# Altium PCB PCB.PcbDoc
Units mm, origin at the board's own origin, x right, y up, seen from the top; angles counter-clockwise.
Board outline 41 x 25.36 mm, 2 copper layers (TOP, BOTTOM), stack 1.586 mm thick; 29 components, 7 nets, 66 pads, 24 vias.
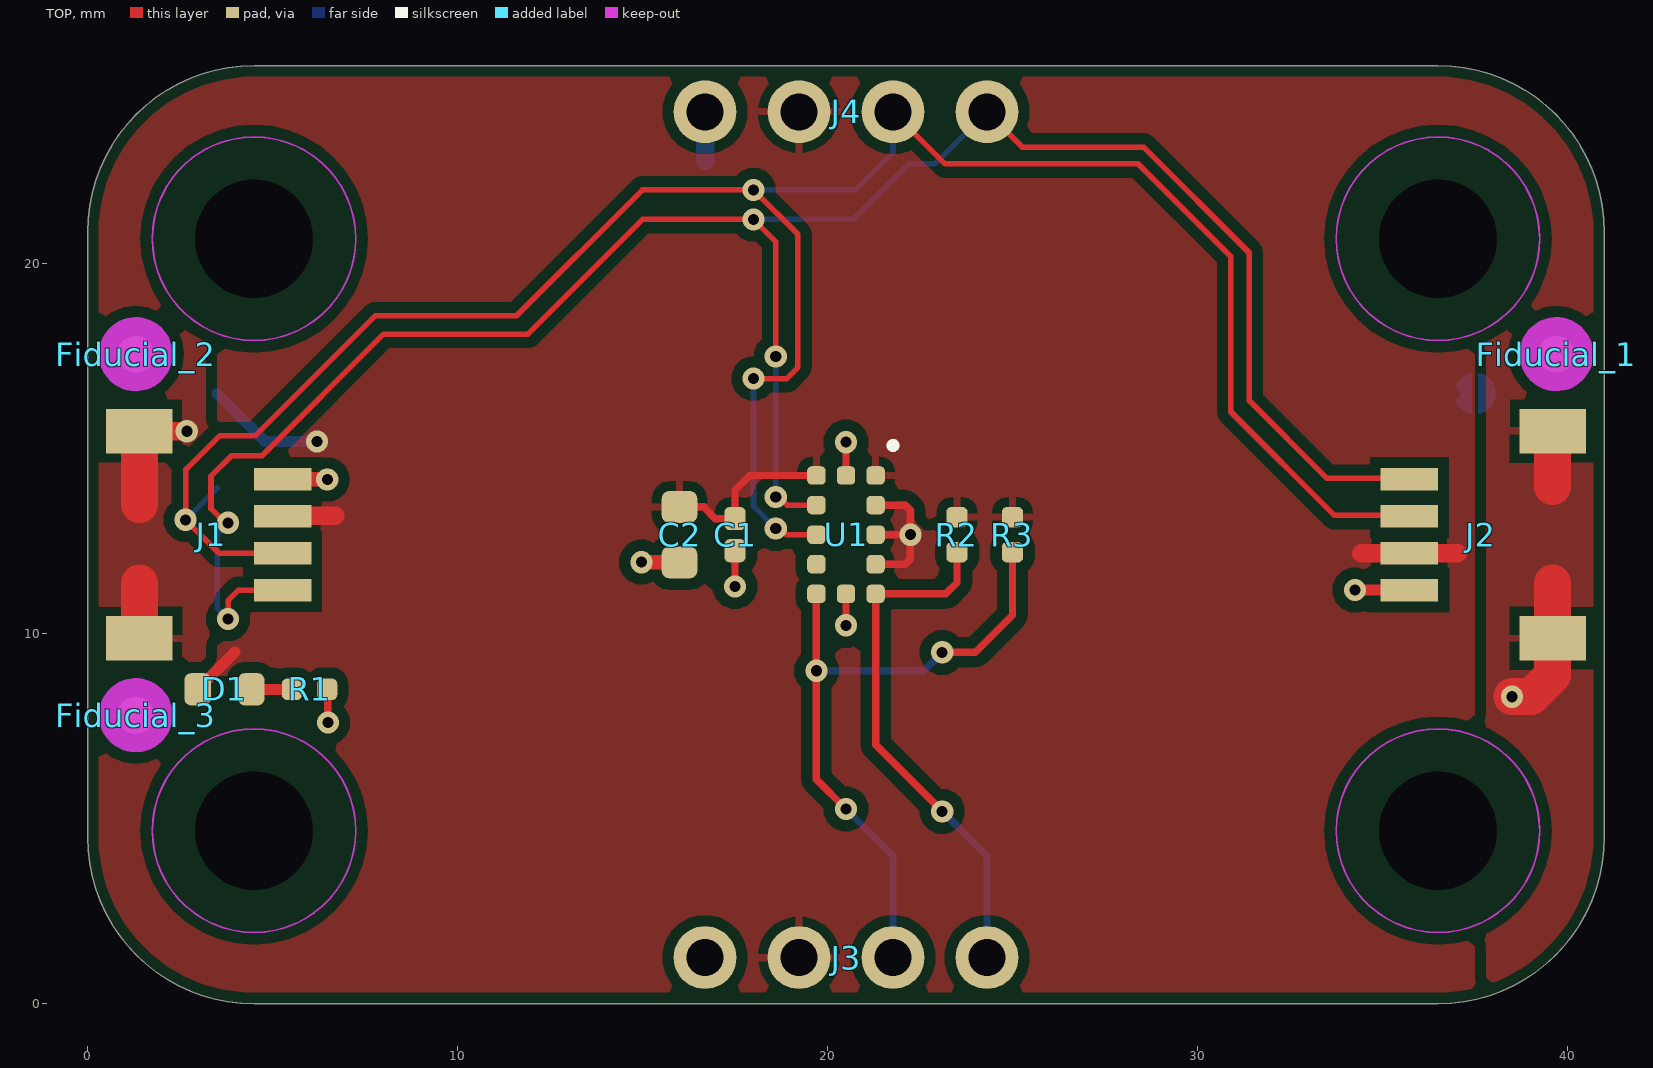
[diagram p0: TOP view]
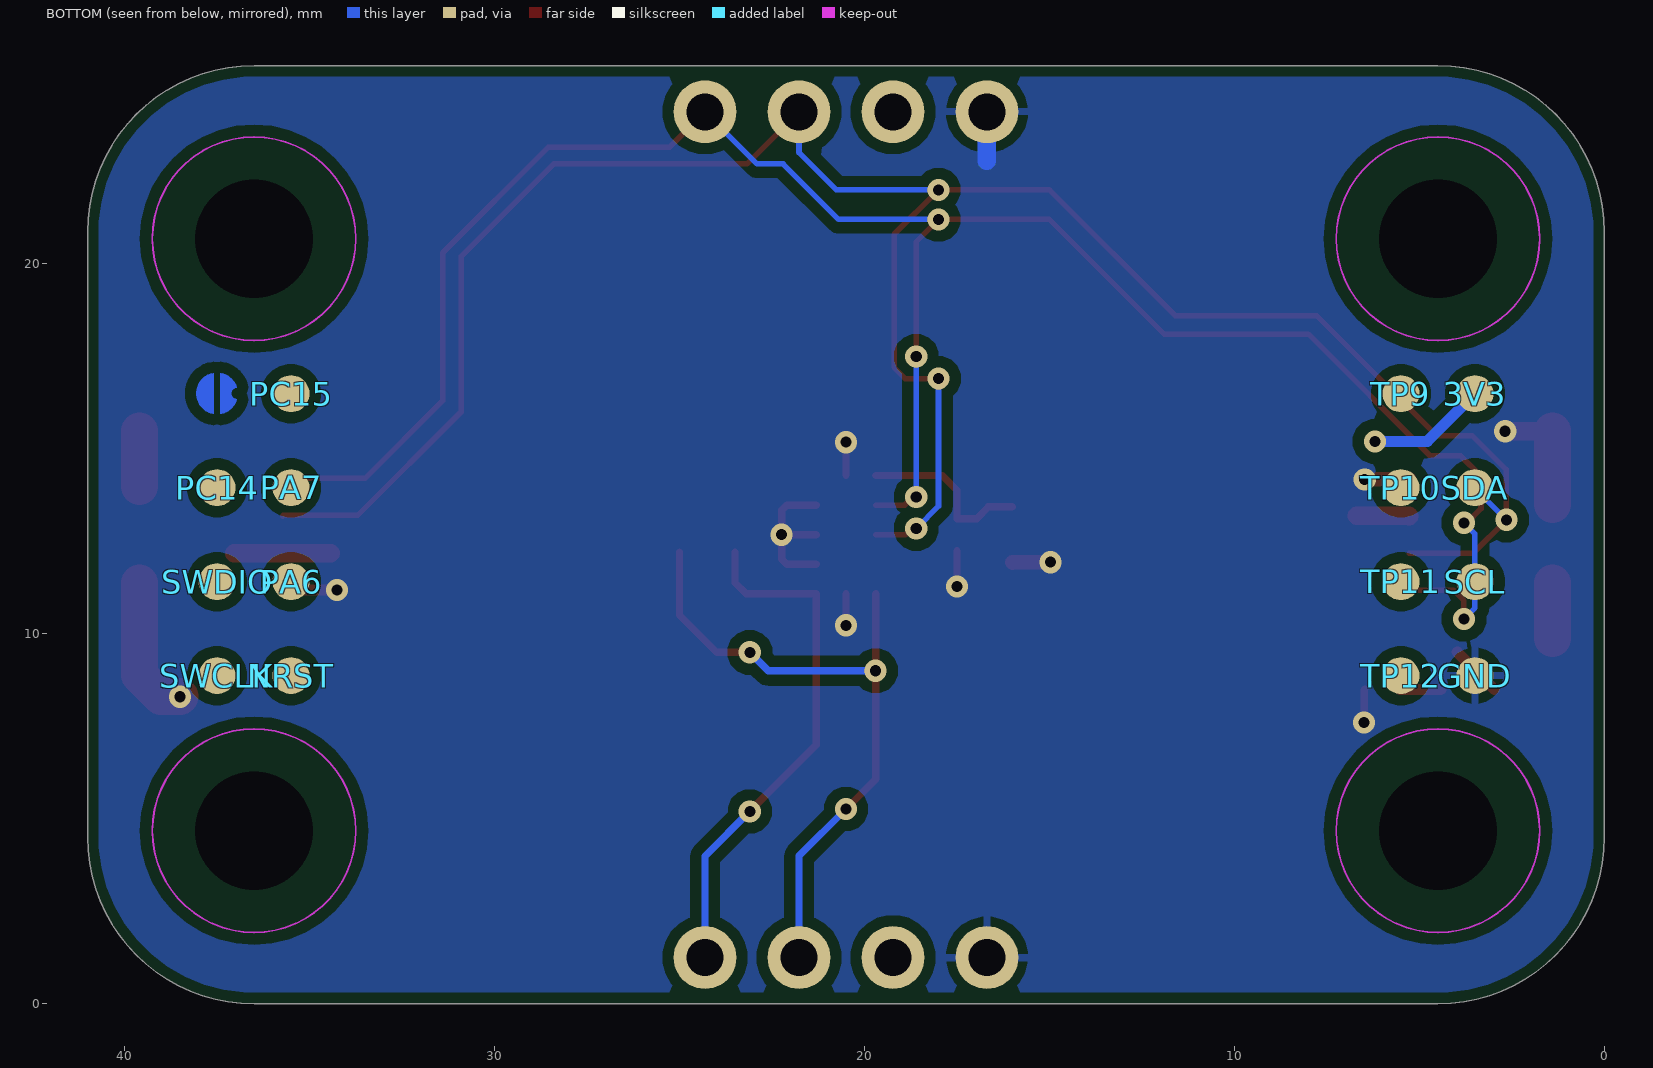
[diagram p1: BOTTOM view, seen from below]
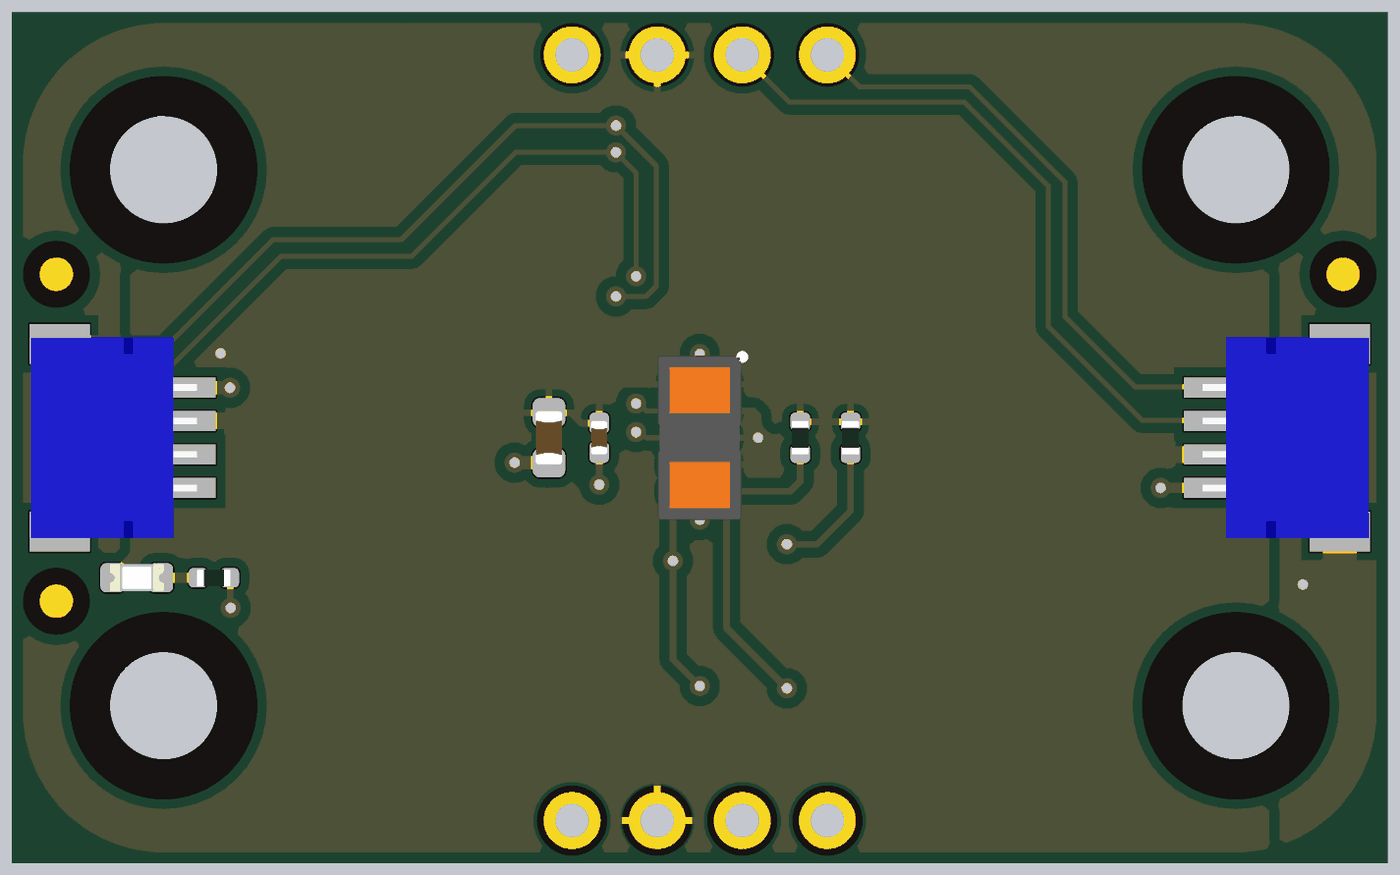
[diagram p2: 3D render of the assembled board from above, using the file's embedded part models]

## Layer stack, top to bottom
Top Solder: solder mask 0.01, Solder Resist, Dk 3.5
TOP: signal copper 0.018
Dielectric: core 1.55, FR-4, Dk 4.8
BOTTOM: signal copper 0.018
Bottom Solder: solder mask 0.01, Solder Resist, Dk 3.5

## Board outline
0,4.5 ccw(c4.5,4.5) 4.5,0 36.5,0 ccw(c36.5,4.5) 41,4.5 41,20.86 ccw(c36.5,20.86) 36.5,25.36 4.5,25.36 ccw(c4.5,20.86) 0,20.86

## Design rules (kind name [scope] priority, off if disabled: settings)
BoardOutlineClearance Mousebites [(ObjectKind = 'Pad') And (Name = 'Free-MOUSEBITE')] p1: gap=0 ignorepadtopadclearanceinfootprint=FALSE
BoardOutlineClearance Silks [(OnLayer('Top Overlay') OR OnLayer('Bottom Overlay'))] p2: gap=0 ignorepadtopadclearanceinfootprint=FALSE
BoardOutlineClearance [All] p3: gap=0.3 ignorepadtopadclearanceinfootprint=FALSE
Clearance COPPER_0.3mm [All] p1: gap=0.127 ignorepadtopadclearanceinfootprint=FALSE except(0.3: Arc-Fill Arc-Poly Arc-Region Track-Fill Track-Poly Track-Region SMDPad-Fill SMDPad-Poly SMDPad-Region THPad-Fill THPad-Poly THPad-Region Via-Fill Via-Poly Via-Region Fill-Fill Fill-Poly Fill-Region Poly-Poly Poly-Region Region-Region)
Clearance "Generic clearance 0.15mm" [All] p2: gap=0.15 ignorepadtopadclearanceinfootprint=FALSE
ComponentClearance [All] p1: gap=0.2 collisioncheckmode=3 verticalgap=0 showdistances=TRUE
DiffPairsRouting USB [InDifferentialPairClass('USB')] p1: maxlimit=0.15 minlimit=0.15 mostfreqgap=0.15 toplayer_minwidth=0.15 toplayer_maxwidth=0.21 toplayer_prefwidth=0.2 bottomlayer_minwidth=0.15 bottomlayer_maxwidth=0.21 bottomlayer_prefwidth=0.2 impedanceprofiledriven=TRUE impedanceprofileid={E6B00C31-4C8E-439C-824F-D2B2CDC26F9C} impedanceprofilevalue=90.000000 maxuncoupledlength=12.7
Height [All] p1: minheight=0 maxheight=30 prefheight=12.7
HoleSize [All] p1: absolutevalues=TRUE maxlimit=30 minlimit=0.3 maxpercent=80.000 minpercent=20.000
HoleToHoleClearance [All] p1: gap=0.25 allowstackedmicrovias=FALSE
MinimumAnnularRing [All] p1: minimumring=0.15
PlaneConnect [All] p1: pad.planeconnectstyle=Relief pad.reliefexpansion=0.508 pad.reliefentries=4 pad.reliefconductorwidth=0.254 pad.reliefairgap=0.254 via.planeconnectstyle=Direct via.reliefexpansion=0.508 via.reliefentries=4 via.reliefconductorwidth=0.254 via.reliefairgap=0.254
PolygonConnect [All] p1: thpad.connectstyle=Relief thpad.reliefconductorwidth=0.2 thpad.reliefentries=4 thpad.polygonreliefangle="90 Angle" thpad.airgapwidth=0.254 smdpad.connectstyle=Relief smdpad.reliefconductorwidth=0.2 smdpad.reliefentries=4 smdpad.polygonreliefangle="90 Angle" smdpad.airgapwidth=0.254 via.connectstyle=Direct via.reliefconductorwidth=0.254 via.reliefentries=4 via.polygonreliefangle="90 Angle" via.airgapwidth=0.254
RoomDefinition TOP [InComponentClass('TOP')] p1: confinementstyle=ConfineIn formatcopy=TRUE lockcomponents=FALSE outline 44.8,6 53.5,6 53.5,18.1 44.8,18.1
RoutingVias StandardVias [All] p1: holewidth=0.3 width=0.6 viastyle="Through Hole" minholewidth=0.3 minwidth=0.6 maxholewidth=0.3 maxwidth=0.6
SMDToCorner [All] p1: distance=39370
SilkToSilkClearance [All] p1: silktosilkclearance=0.2
SilkToSolderMaskClearance [IsPad] p1: minsilkscreentomaskgap=0.15 clearancetoexposedcopper=TRUE
SolderMaskExpansion VIAtented [IsVia] p1: expansion=0.102 istentingtop=TRUE
SolderMaskExpansion [All] p2: expansion=0.05 istentingtop=FALSE
UnConnectedPin [All] p1:
UnRoutedNet [NOT WithinRoom('K36')] p1: checkbadconnections=TRUE
ViasUnderSMD [All] p1: allowed=FALSE
Width StandardTraces [All] p1: maxlimit=5 minlimit=0.15 preferedwidth=0.15 minimp=50.000000 maximp=50.000000 favimp=50.000000
21 further rules are at their usual default settings.

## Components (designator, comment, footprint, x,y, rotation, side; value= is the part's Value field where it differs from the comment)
3V3 "Test point 1.00mm" TP-1.00MM 3.5,16.49 r90 bottom
C1 "0402B104K160CT" CAP-0402 17.5,12.68 r270 top value=100nF
C2 "GRM188R61C475KAAJD" CAP-0603 16,12.68 r90 top value=4.7µF
D1 "HSMG-C190" LEDC1608X80N-AK 3.7,8.5 r180 top
Fiducial_1 "Fiducial mark 1mm" "Fiducial mark 1mm-Footprint-1" 39.7,17.56 r270 top
Fiducial_2 "Fiducial mark 1mm" "Fiducial mark 1mm-Footprint-1" 1.3,17.56 r270 top
Fiducial_3 "Fiducial mark 1mm" "Fiducial mark 1mm-Footprint-1" 1.3,7.8 r270 top
GND "Test point 1.00mm" TP-1.00MM 3.5,8.87 r90 bottom
J1 "SM04B-SRSS-TB(LF)(SN)" SM04B-SRSS-TB(LF)(SN)-Footprint-1 3.337,12.68 r90 top locked
J2 "SM04B-SRSS-TB(LF)(SN)" SM04B-SRSS-TB(LF)(SN)-Footprint-1 37.663,12.68 r270 top locked
J3 "HEADER TH 2.54mm VERT. 1x004POS" "PIN HEADER 2.54mm VERT. 1x4POS-Footprint-1"#1 20.5,1.25 r0 top
J4 "HEADER TH 2.54mm VERT. 1x004POS" "PIN HEADER 2.54mm VERT. 1x4POS-Footprint-1"#2 20.5,24.11 r0 top
NRST "Test point 1.00mm" TP-1.00MM 35.5,8.87 r180 bottom
PA6 "Test point 1.00mm" TP-1.00MM 35.5,11.41 r180 bottom
PA7 "Test point 1.00mm" TP-1.00MM 35.5,13.95 r180 bottom
PC14 "Test point 1.00mm" TP-1.00MM 37.5,13.95 r180 bottom
PC15 "Test point 1.00mm" TP-1.00MM 35.5,16.49 r180 bottom
R1 "CRCW04021K00FKEDC" RES-0402 6,8.5 r180 top value=1k
R2 "CRCW040210K0FKED" RES-0402 23.5,12.68 r270 top value=10k
R3 "CRCW040210K0FKED" RES-0402 25,12.68 r90 top value=10k
SCL "Test point 1.00mm" TP-1.00MM 3.5,11.41 r90 bottom
SDA "Test point 1.00mm" TP-1.00MM 3.5,13.95 r90 bottom
SWCLK "Test point 1.00mm" TP-1.00MM 37.5,8.87 r180 bottom
SWDIO "Test point 1.00mm" TP-1.00MM 37.5,11.41 r180 bottom
TP9 "Test point 1.00mm" TP-1.00MM 5.5,16.49 r0 bottom
TP10 "Test point 1.00mm" TP-1.00MM 5.5,13.95 r0 bottom
TP11 "Test point 1.00mm" TP-1.00MM 5.5,11.41 r0 bottom
TP12 "Test point 1.00mm" TP-1.00MM 5.5,8.87 r0 bottom
U1 "VL53L4CDV0DH/1" VL53L4CDV0DH/1 20.5,12.68 r90 top

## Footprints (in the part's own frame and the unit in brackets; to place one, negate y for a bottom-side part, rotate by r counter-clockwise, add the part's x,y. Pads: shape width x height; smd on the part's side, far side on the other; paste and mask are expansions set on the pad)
CAP-0402 [mm] "Chip Capacitor, 2-Leads, Body  0402 (in) 1005 (mm), IPC Medium Density"
  rrect52% 0.63x0.58 smd mask+0.05: 1(-0.435,0) 2(0.435,0)
  body extent -0.5,-0.25 0.5,0.25, height 0.5
CAP-0603 [mm] "Chip Capacitor, Body 0603 imperial,1.6x0.8mm, IPC High Density"
  rrect51% 0.87x0.97 smd mask+0.05: 1(-0.75,0) 2(0.75,0)
  body extent -0.8,-0.4 0.8,0.4, height 0.8
"Fiducial mark 1mm-Footprint-1" [mm]
  round 1 smd paste-10 mask+0.5: 1(0,0)
  TOP keep-out circle w1: c0,0 r0.5
LEDC1608X80N-AK [mm]
  rrect50% 0.72x0.87 smd: A(0.725,0) C(-0.725,0)
  body extent -0.8,-0.4 0.8,0.4, height 0.79
"PIN HEADER 2.54mm VERT. 1x4POS-Footprint-1"#1 [mm]
  round 1.7 hole 1 mask+0.2: 1(-3.81,0) 2(-1.27,0) 3(1.27,0) 4(3.81,0)
"PIN HEADER 2.54mm VERT. 1x4POS-Footprint-1"#2 [mm]
  round 1.7 hole 1 mask+0.1: 1(-3.81,0) 2(-1.27,0) 3(1.27,0) 4(3.81,0)
RES-0402 [mm] "Chip Resistor, 2-Leads, Body  0402 (in) 1005 (mm), IPC Medium Density"
  rrect51% 0.55x0.58 smd mask+0.05: 1(-0.475,0) 2(0.475,0)
  body extent -0.5,-0.25 0.5,0.25, height 0.34
SM04B-SRSS-TB(LF)(SN)-Footprint-1 [mm]
  rect 0.6x1.55 smd mask+0.05: 1(1.5,-1.937) 2(0.5,-1.937) 3(-0.5,-1.937) 4(-1.5,-1.937)
  rect 1.2x1.8 smd mask+0.05: FIX(-2.8,1.938) FIX(2.8,1.938)
  body extent -3,-2.16 3,2.8, height 2.98
TP-1.00MM [mm]
  rrect100% 1x1 smd paste-2.54: X(0,0)
VL53L4CDV0DH/1 [mm]
  rrect50% 0.5x0.5 smd mask+0.07: 1(1.6,-0.8) 2(0.8,-0.8) 3(0,-0.8) 4(-0.8,-0.8) 5(-1.6,-0.8) 6(-1.6,0) 7(-1.6,0.8) 8(-0.8,0.8) 9(0,0.8) 10(0.8,0.8) 11(1.6,0.8) 12(1.6,0)
  silkscreen extent 2.36,-1.32 2.46,-1.22, body extent -2.45,-1.25 2.45,1.25, height 1.6

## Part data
3V3 GND NRST PA6 PA7 PC14 PC15 SCL SDA SWCLK SWDIO TP9 TP10 TP11 TP12: library part UT0013-A.6, Manufacturer="This is not a component"
C1: library part C0012-A.15, "CAP CHIP 0402 100nF 10% 16V X7R", Case Code (Imperial)=0402, Dielectric=X7R, Manufacturer=Walsin, Tolerance=10%, Voltage=16V
C2: library part C0054-A.16, "CAP CHIP 0603 4.7uF 10% 16V X5R", Case Code (Imperial)=0603, Dielectric=X5R, Manufacturer=Murata, Manufacturer 3="Samsung Electro-Mechanics", Part number 2=GRM188R61C475KE11D, Part number 3=CL10A475KO8NNNC, Tolerance=10%, Voltage=16V
D1: library part L0009-A.5, "LED SMD 0603 GREEN/568 15mcd 120^", Manufacturer=Broadcom
Fiducial_1 Fiducial_2 Fiducial_3: library part UT0023-A.7, "Fiducial mark 1mm clearance 2mm"
J1 J2: library part J0005-A.2, "CONN JST 4POS SIDE 1MM TIN QWIIC", Manufacturer=JST
J3 J4: library part J0162-A.5
R1: library part R0007-A.24, "RES CHIP 0402 1k 1% 1/16W", Case Code (Imperial)=0402, Manufacturer=Vishay, Power=62.5mW, Temperature Coefficient=100ppm, Tolerance=1%
R2 R3: library part R0003-A.24, "RES CHIP 0402 10k 1% 1/16W", Case Code (Imperial)=0402, Manufacturer=Vishay, Power=62.5mW, Temperature Coefficient=100ppm, Tolerance=1%
U1: library part U0380-A.2, "SENSOR TOF, 940nm, single supply 2.6V to 3.5V, I2C, 0 to 1300mm, FOV 18°, LGA12 4.4x2.4x1mm", Manufacturer="ST Microelectronics"

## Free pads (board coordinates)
  round 3 hole 3.2 unplated paste-2539.97 mask+1.3: MH(4.5,4.68) MH(4.5,20.68) MH(36.5,4.68) MH(36.5,20.68)

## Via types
v1: diameter 0.6, hole 0.3, TOP to BOTTOM, tented both sides, 24 vias

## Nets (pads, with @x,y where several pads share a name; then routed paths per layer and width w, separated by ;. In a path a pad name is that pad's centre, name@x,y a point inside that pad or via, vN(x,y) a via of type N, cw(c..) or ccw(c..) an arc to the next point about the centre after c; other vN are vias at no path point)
+3V3: 3V3.X C1.1 C2.2 D1.A J1.2 J2.2 J3.2 J4.2 R2.1 R3.2 U1.1 U1.11 | length 13.4
  TOP w0.2: C2.2 16.65,13.43 16.965,13.115 C1.1 17.5,13.88 17.9,14.28 U1.11
  TOP w0.3: D1.A 3.98,9.505
  TOP w0.5: J1.2 5.284,13.19 6.69,13.19 ; 34.42,12.18 J2.2 37.031,12.18
  BOTTOM w0.3: 3V3.X 4.79,15.2 v1(6.2,15.2)
GND: C1.2 C2.1 GND.X J1.1 J1.FIX J2.1 J2.FIX J3.1 J4.1 R1.1 U1.2 U1.3 U1.4 U1.6 U1.12 | length 23
  TOP w0.2: R1.1 6.488,8.488 6.488,7.612 v1(6.5,7.6) ; v1(17.5,11.28) C1.2 ; v1(20.5,10.23) U1.6 ; U1.12 v1(20.5,15.18) ; U1.4 22.1,11.88 22.241,12.021 v1(22.241,12.68) ; U1.3 v1(22.241,12.68) ; U1.2 22.1,13.48 22.241,13.339 v1(22.241,12.68)
  TOP w0.3: v1(34.255,11.183) 34.256,11.182 35.724,11.182 J2.1
  TOP w0.4: J1.1 5.279,14.176 6.477,14.176 v1(6.481,14.171) ; v1(14.975,11.937) 14.978,11.933 15.997,11.933 C2.1
  TOP w0.5: J1.FIX@1.399,15.48 2.678,15.48 v1(2.683,15.475)
  TOP w1: J1.FIX@1.399,9.88 1.399,11.379 ; 1.399,13.499 J1.FIX@1.399,15.48 ; v1(38.5,8.3) 39.015,8.3 39.601,8.886 J2.FIX@39.601,9.88 ; J2.FIX@39.6,9.881 39.6,11.38 ; 39.601,13.981 J2.FIX@39.601,15.48
  BOTTOM w0.5: 16.69,22.79 J4.1
GPIO1_1: J3.3 R3.1 U1.7 | length 18.3
  TOP w0.2: U1.7 v1(19.7,9.003) 19.7,6.067 v1(20.5,5.267) ; v1(23.1,9.5) 24,9.5 25,10.5 R3.1
  BOTTOM w0.2: v1(19.7,9.003) 22.603,9.003 v1(23.1,9.5) ; v1(20.5,5.267) 21.77,3.997 J3.3
NetD1_C: D1.C R1.2 | length 1.1
  TOP w0.3: D1.C R1.2
SCL_1: J1.4 J2.4 J4.4 SCL.X U1.10 | length 58.3
  TOP w0.15: v1(3.8,10.4) 3.8,10.9 4.08,11.18 J1.4 ; v1(3.8,13) 3.723,13 3.337,13.386 3.337,14.262 3.888,14.813 4.713,14.813 7.999,18.099 11.9,18.099 15.001,21.2 v1(18,21.2) 18.6,20.6 v1(18.6,17.5) ; v1(18.6,13.7) 18.693,13.7 18.913,13.48 U1.10 ; J4.4 25.263,23.157 28.543,23.157 31.4,20.3 31.4,16.302 33.502,14.2 35.706,14.2 J2.4
  BOTTOM w0.15: v1(3.8,10.4) 3.5,10.7 3.5,12.7 v1(3.8,13) ; v1(18,21.2) 20.7,21.2 22.2,22.7 22.9,22.7 J4.4 ; v1(18.6,13.7) v1(18.6,17.5)
SDA_1: J1.3 J2.3 J4.3 SDA.X U1.9 | length 62.4
  TOP w0.15: 2.65,14.45 v1(2.65,13.082) 3.554,12.178 3.895,12.178 3.897,12.18 J1.3 ; 2.66,14.44 3.569,15.349 4.531,15.349 7.782,18.6 11.6,18.6 15,22 v1(18,22) 19.2,20.8 19.2,17.2 18.9,16.9 v1(18,16.9) ; v1(18.6,12.85) 18.722,12.85 18.892,12.68 U1.9 ; J4.3 23.18,22.7 28.4,22.7 30.9,20.2 30.9,16.002 33.702,13.2 35.706,13.2 J2.3
  BOTTOM w0.15: v1(2.65,13.082) 3.5,13.932 SDA.X ; v1(18,16.9) 18,13.45 v1(18.6,12.85) ; v1(18,22) 20.76,22 21.77,23.01 J4.3
XSHUT_1: J3.4 R2.2 U1.5 | length 14.2
  TOP w0.2: v1(23.1,5.2) 21.3,7 U1.5 23.2,11.08 23.5,11.38 R2.2
  BOTTOM w0.2: v1(23.1,5.2) 24.31,3.99 J3.4
pads on no net: Fiducial_1.1 Fiducial_2.1 Fiducial_3.1 NRST.X PA6.X PA7.X PC14.X PC15.X SWCLK.X SWDIO.X TP9.X TP10.X TP11.X TP12.X U1.8

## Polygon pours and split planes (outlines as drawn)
GND on TOP "NONET_L04_P-001" (solid, remove dead copper, pour order 3): 0,4.5 ccw(c4.5,4.5) 4.5,0 36.5,0 ccw(c36.5,4.5) 41,4.5 41,20.86 ccw(c36.5,20.86) 36.5,25.36 4.5,25.36 ccw(c4.5,20.86) 0,20.86
+3V3 on TOP "NONET_L04_P-001" (solid, remove dead copper, pour order 2): 0,4.5 ccw(c4.5,4.5) 4.5,0 36.5,0 ccw(c36.5,4.5) 41,4.5 41,20.86 ccw(c36.5,20.86) 36.5,25.36 4.5,25.36 ccw(c4.5,20.86) 0,20.86
GND on TOP "NONET_L04_P-001" (solid, remove dead copper, pour order 1): 0,25.36 0,0 3.2,0 3.2,25.36
GND on TOP "NONET_L04_P-001" (solid, remove dead copper, pour order 0): 41,25.36 41,0 37.8,0 37.8,25.36
GND on BOTTOM "NONET_L04_P-001" (solid, remove dead copper, pour order 4): 0,4.5 ccw(c4.5,4.5) 4.5,0 36.5,0 ccw(c36.5,4.5) 41,4.5 41,20.86 ccw(c36.5,20.86) 36.5,25.36 4.5,25.36 ccw(c4.5,20.86) 0,20.86

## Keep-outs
Keep-Out Layer:
  circle w0.05: c36.5,4.68 r2.75
  circle w0.05: c36.5,20.68 r2.75
  circle w0.05: c4.5,4.68 r2.75
  circle w0.05: c4.5,20.68 r2.75

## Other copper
BOTTOM:
  region: 333 vertices and 0 holes, not listed, extent 36.965,15.947 37.415,17.049
  region: 283 vertices and 0 holes, not listed, extent 37.591,15.947 38.059,17.049

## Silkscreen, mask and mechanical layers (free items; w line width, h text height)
Route Tool Path:
  lines w2: -1,8.498 -1,16.86 ; 42,4.5 cw(c36.5,4.5) 36.5,-1 ; 42,8.498 42,16.86 ; -1,4.498 ccw(c4.5,4.5) 4.498,-1 ; -1,4.498 cw(c4.5,4.5) -1,4.5 ccw(c0,4.5) -1,4.498 ; -1,20.86 cw(c4.5,20.86) 4.5,26.36 ; -1,20.86 -1,20.86 ; 4.498,-1 ccw(c4.5,4.5) 4.5,-1 ; 4.498,-1 ccw(c4.5,0) 4.5,-1 ; 4.5,-1 36.5,-1 ; 4.5,26.36 36.5,26.36 ; 4.5,26.36 4.5,26.36 ; 36.5,-1 36.5,-1 ; 36.5,26.36 cw(c36.5,20.86) 36.502,26.36 ; 36.5,26.36 cw(c36.5,25.36) 36.502,26.36 ; 36.502,26.36 cw(c36.5,20.86) 42,20.863 ; 42,20.863 cw(c41,20.86) 42,20.86 ccw(c36.5,20.86) 42,20.863
Board:
  the board outline again, w0.05
Mechanical 33:
  lines w0.05: 8.44,1.25 9.07,1.25 ; 9.07,0.62 9.07,1.25 ; 9.07,1.88 9.07,1.25 ; 9.7,1.25 9.07,1.25 ; 10.98,1.25 11.61,1.25 ; 11.61,0.62 11.61,1.25 ; 11.61,1.88 11.61,1.25 ; 12.24,1.25 11.61,1.25 ; 13.52,1.25 14.15,1.25 ; 14.15,0.62 14.15,1.25 ; 14.15,1.88 14.15,1.25 ; 14.78,1.25 14.15,1.25 ; 16.06,1.25 16.69,1.25 ; 16.06,24.11 16.69,24.11 ; 16.69,0.62 16.69,1.25 ; 16.69,1.88 16.69,1.25 ; 16.69,23.48 16.69,24.11 ; 16.69,24.74 16.69,24.11 ; 17.32,1.25 16.69,1.25 ; 17.32,24.11 16.69,24.11 ; 18.6,1.25 19.23,1.25 ; 18.6,24.11 19.23,24.11 ; 19.23,0.62 19.23,1.25 ; 19.23,1.88 19.23,1.25 ; 19.23,23.48 19.23,24.11 ; 19.23,24.74 19.23,24.11 ; 19.86,1.25 19.23,1.25 ; 19.86,24.11 19.23,24.11 ; 21.14,1.25 21.77,1.25 ; 21.14,24.11 21.77,24.11 ; 21.77,0.62 21.77,1.25 ; 21.77,1.88 21.77,1.25 ; 21.77,23.48 21.77,24.11 ; 21.77,24.74 21.77,24.11 ; 22.4,1.25 21.77,1.25 ; 22.4,24.11 21.77,24.11 ; 23.68,1.25 24.31,1.25 ; 23.68,24.11 24.31,24.11 ; 24.31,0.62 24.31,1.25 ; 24.31,1.88 24.31,1.25 ; 24.31,23.48 24.31,24.11 ; 24.31,24.74 24.31,24.11 ; 24.94,1.25 24.31,1.25 ; 24.94,24.11 24.31,24.11 ; 26.22,1.25 26.85,1.25 ; 26.85,0.62 26.85,1.25 ; 26.85,1.88 26.85,1.25 ; 27.48,1.25 26.85,1.25 ; 28.76,1.25 29.39,1.25 ; 29.39,0.62 29.39,1.25 ; 29.39,1.88 29.39,1.25 ; 30.02,1.25 29.39,1.25 ; 31.3,1.25 31.93,1.25 ; 31.93,0.62 31.93,1.25 ; 31.93,1.88 31.93,1.25 ; 32.56,1.25 31.93,1.25
Mechanical 66:
  circle w0.05: c36.5,4.68 r2.85
  circle w0.05: c36.5,20.68 r2.85
  circle w0.05: c4.5,20.68 r2.85
  circle w0.05: c4.5,4.68 r2.85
